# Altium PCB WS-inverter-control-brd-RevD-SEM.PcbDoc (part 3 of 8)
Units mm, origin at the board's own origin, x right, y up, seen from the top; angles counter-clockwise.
Board outline 270 x 105.92 mm, 6 copper layers (Top Layer, Int1 (Sign), Int2 (PWR), Int3 (GND), Int4 (Sign), Bottom Layer), stack 1.509 mm thick; 709 components, 375 nets, 2377 pads, 1332 vias.
Unrouted connection lines stored in the file: 55.
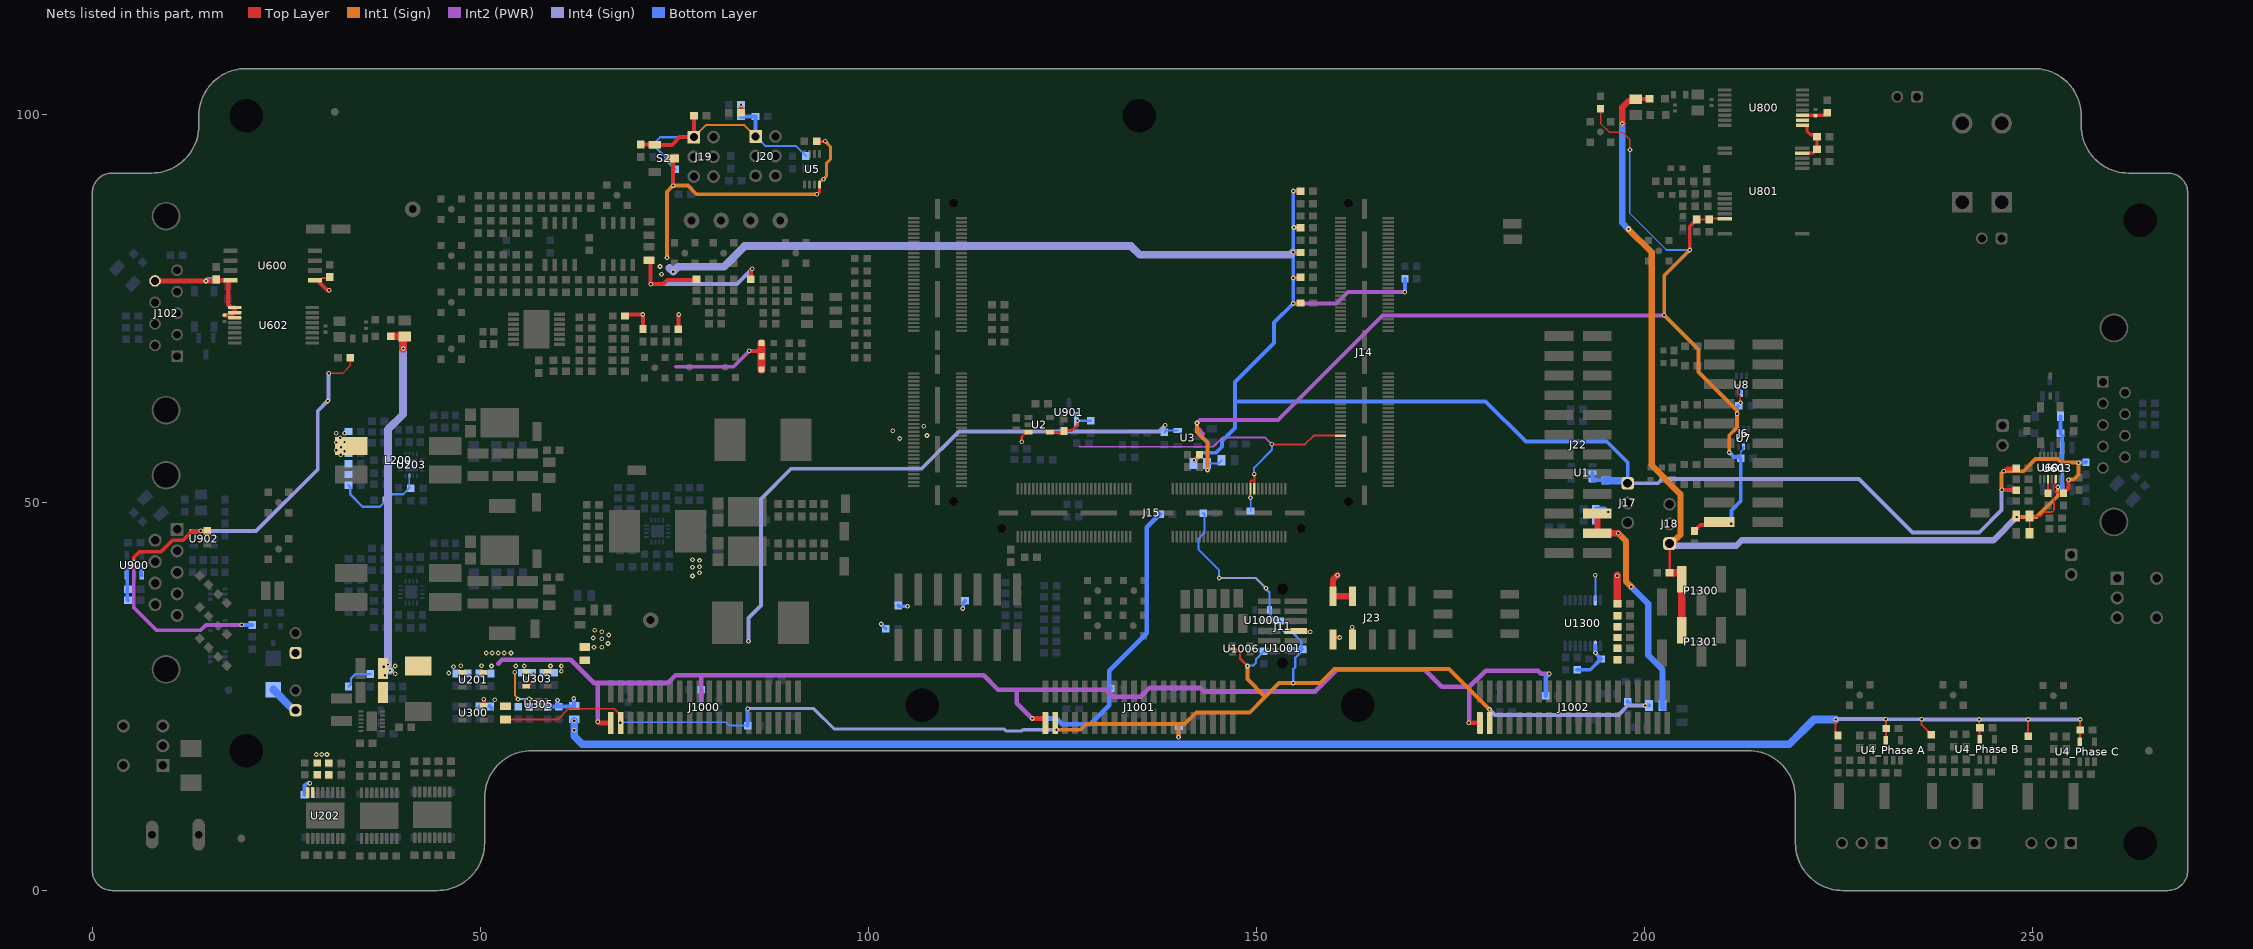
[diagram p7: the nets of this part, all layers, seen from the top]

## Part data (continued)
J107 J108: library part CMP-0093760-1, "Connector Header Through Hole 3 position 0.200\" (5.08mm)", Digikey Part Number=HPM-03-01-T-S-ND, Manufacturer=Samtec, Mouser Part Number=200-HPM0301TS, Operating Temperature Range="-55°C to +105°C"
J109 J110: library part CMP-0054970-1, "Header, 2.54mm, 2x1, Tin, TH", Color=Natural, Current_A=5A, Manufacturer="TE Connectivity", Supplier Part Number 1=A1921-ND, Voltage_V=250V
J600 J601: library part CMP-0075405-3, "Header, 100mil, 2x1, Gold, TH", Color=Black, Current_A=6.3A, Manufacturer=Samtec, Supplier Part Number 1=SAM1029-02-ND, Voltage_V=550V
J1000 J1001 J1002: library part CMP-0092627-1, "Connector Header Surface Mount 40 position 0.050\" (1.27mm)", Digikey Part Number=SAM11069-ND, Manufacturer=Samtec, Mouser Part Number=200-ESHF12001LDSM, Operating Temperature Range="-55°C to +125°C"
L200 L301: library part CMP-0080788-1, "Coupled inductor, 47 µH, 7.5 A, 0.065 ohm, SMD", Manufacturer=Coilcraft, ValueDisplayed=47µH
L300: library part CMP-0063383-1, "Inductor, Shielded, 2.2 uH, 8.1 A, 0.0183 ohm, AEC-Q200 Grade 1, SMD", Manufacturer=Vishay-Dale, Supplier Part Number 1=IHLP2525CZER2R2M5A-ND, Value1="0.0183 ohm", Value2=8.1A, ValueDisplayed=2.2uH
L400: library part CMP-0060638-1, "Inductor, Shielded Drum Core, Ferrite, 10 uH, 5.7 A, 0.02 ohm, SMD", Manufacturer=Coilcraft, Supplier Part Number 1=994-MSS1278T-103MLB, Value1="0.02 ohm", Value2=5.7A, ValueDisplayed=10uH
L401 L402: library part CMP-0061523-2, "Inductor, Shielded Drum Core, Ferrite, 22 uH, 4 A, 0.04 ohm, SMD", Manufacturer=Coilcraft, Supplier Part Number 1=994-MSS1278T-223MLB, Value1="0.04 ohm", Value2=4A, ValueDisplayed=22uH
L600 L601: library part CMP-0062430-2, "Inductor, Ferrite, 100 uH, 0.15 A, 2 ohm, SMD", Manufacturer=TDK, Supplier Part Number 1=445-3959-1-ND, Value1="2 ohm", Value2=0.15A, ValueDisplayed=100uH
L602 L800: library part CMP-1392-00025-2, Ambient Temperature Range High=85°C, Ambient Temperature Range Low=-40°C, Case/Package=SMD/SMT, Current Rating=550mA, DC Resistance (DCR)=300mΩ, Inductance=2.2µH, Manufacturer="Wurth Elektronik", Max Operating Temperature=125°C
LBL1200: library part CMP-0003625-1, "Thermal Transfer Printable Labels, 0.650\" W x 0.200\" H - 10,000 per roll", Manufacturer=Brady, Supplier Part Number 1=97C5133
LOGO1200: library part CMP-0074835-1, "IEC 61010-1 High Voltage Warning"
Logo1201: library part CMP-0074847-1, "FCC_disclaimer"
Logo1202: library part CMP-0074838-1, "Texas Instrument Corporate Signature"
Logo1203: library part CMP-0074769-1
NT200 NT300 NT400: library part CMP-0078142-6, "Single point connection between nets.", Manufacturer=N/A
P1300 P1301: library part CMP-1024-00239-1, "0.025\" SQ Post Header, Surface Mount, Vertical, -55 to 105 degC, 2.54 mm Pitch, 5-Pin, Male, RoHS", Manufacturer=Samtec, Temperature Range="-55 to 105 degC"
Q900: library part CMP-0077248-1, "MOSFET, N-CH, 20 V, 2.3 A, AEC-Q101, SOT-23", Alternate Manufacturer=None, Manufacturer="Infineon Technologies", Supplier Part Number 1=BSS806NEH6327XTSA1CT-ND, Value1="? ohm", Value2="1.7 nC"
"R1_Phase A" "R1_Phase B" "R1_Phase C" "R3_Phase A" "R3_Phase B" "R3_Phase C" R13 R25 R27 R28 R29 R30 R503 R504 R513 R521 R526 R527 R538 R545 R546 R550 R551 R562 R563 R564 R566 R568 R569 R600 R601 R608 R610 R804 R1000 R1001 R1002 R1003 R1004 R1005 R1006 R1007 R1008 R1009 R1010 R1011 R1012 R1013 R1014 R1015 R1016 R1017 R1018 R1034 R1036 R1040 R1042 R1304 Rjldc1 Rjldc2: library part CMP-0025697-4, "RES, 0, 5%, 0.1 W, AEC-Q200 Grade 0, 0603", Manufacturer=Vishay-Dale, Power_W=100mW, Supplier Part Number 1=541-0.0GCT-ND, TempCo="200 ppm/C", Tolerance_%=5%, Value2=0.1W, Value_Code=0000, ValueDisplayed=0
R2 R6: library part CMP-0022736-4, "RES, 100, 1%, 0.1 W, 0603", Manufacturer=Yageo, Power_W=100mW, Supplier Part Number 1=311-100HRCT-ND, TempCo="100 ppm/C", Tolerance_%=1%, Value2=0.1W, Value_Code=100R, ValueDisplayed=100
R4 R5 R31 R32 R33 R34 R35 R36 R37 R38 R39 R40 R41 R42 R43 R44 R45 R46 R47 R48 R49 R50 R51 R52 R53 R54 R55 R56 R57 R58 R308 R319 R320 R322 R505 R506 R507 R508 R509 R510 R516 R517 R529 R534 R548 R552 R553 R554 R555 R558 R559 R560 R561 R606 R613 R617 R618 R619 R905 R907 R1019 R1020 R1021 R1022 R1023 R1024 R1027 R1030: library part CMP-0021998-4, "RES, 10.0 k, 1%, 0.1 W, AEC-Q200 Grade 0, 0603", Manufacturer=Vishay-Dale, Power_W=100mW, Supplier Part Number 1=541-10.0KHCT-ND, TempCo="100 ppm/C", Tolerance_%=1%, Value2=0.1W, Value_Code=10k0, ValueDisplayed=10.0k
R7 R11 R12 R18 R514 R528 R547 R565 R570 R904: library part CMP-0081280-1, "RES, 47.0, 1%, 0.1 W, AEC-Q200 Grade 0, 0603", Manufacturer=Vishay-Dale, Power_W=100mW, Supplier Part Number 1=541-47.0HCT-ND, TempCo="100 ppm/C", Tolerance_%=1%, Value2=0.1W, Value_Code=47R0, ValueDisplayed=47.0
R8 R26: library part CMP-0022455-4, "RES, 4.64 k, 1%, 0.1 W, AEC-Q200 Grade 0, 0603", Manufacturer=Vishay-Dale, Power_W=100mW, Supplier Part Number 1=541-4.64KHCT-ND, TempCo="100 ppm/C", Tolerance_%=1%, Value2=0.1W, Value_Code=4k64, ValueDisplayed=4.64k
R9 R10 "R20_Phase A" "R20_Phase B" "R20_Phase C" R604 R609 R614 R615 R616: library part CMP-0022003-4, "RES, 10.0, 1%, 0.1 W, AEC-Q200 Grade 0, 0603", Manufacturer=Vishay-Dale, Power_W=100mW, Supplier Part Number 1=541-10.0HCT-ND, TempCo="100 ppm/C", Tolerance_%=1%, Value2=0.1W, Value_Code=10R0, ValueDisplayed=10.0
R10jump R103 R104 R105 R106 R113 R114 R115 R116 R324 R325 R539 R541 Rjump12v Rjumppre: library part CMP-0020833-2, "RES, 0, 1%, 0.5 W, 0805", Manufacturer=Keystone, Power_W=500mW, Supplier Part Number 1=36-5106CT-ND, TempCo=ppm/C, Tolerance_%=1%, Value2=0.5W, Value_Code=0
R14 R520 R525 R537 R544 R900 R906: library part CMP-0021991-4, "RES, 100, 1%, 0.1 W, AEC-Q200 Grade 0, 0603", Manufacturer=Vishay-Dale, Power_W=100mW, Supplier Part Number 1=541-100HCT-ND, TempCo="100 ppm/C", Tolerance_%=1%, Value2=0.1W, Value_Code=100R, ValueDisplayed=100
R15 R16 R59: library part CMP-0025817-4, "RES, 4.7 k, 5%, 0.1 W, AEC-Q200 Grade 0, 0603", Manufacturer=Vishay-Dale, Power_W=100mW, Supplier Part Number 1=541-4.7KGCT-ND, TempCo="200 ppm/C", Tolerance_%=5%, Value2=0.1W, Value_Code=4k70, ValueDisplayed=4.7k
R17: library part CMP-0022115-4, "RES, 1.15 k, 1%, 0.1 W, AEC-Q200 Grade 0, 0603", Manufacturer=Vishay-Dale, Power_W=100mW, Supplier Part Number 1=541-1.15KHCT-ND, TempCo="100 ppm/C", Tolerance_%=1%, Value2=0.1W, Value_Code=1k15, ValueDisplayed=1.15k
"R19_Phase A" "R19_Phase B" "R19_Phase C" "R21_Phase A" "R21_Phase B" "R21_Phase C": library part CMP-0078581-1, "RES, 1.00 k, 0.1%, 0.1 W, AEC-Q200 Grade 0, 0603", Manufacturer=Panasonic, Power_W=100mW, Supplier Part Number 1=P1.0KDBCT-ND, TempCo="25 ppm/C", Tolerance_%=0.1%, Value2=0.1W, Value_Code=1k00, ValueDisplayed=1.00k
"R22_Phase A" "R22_Phase B" "R22_Phase C" R321: library part CMP-0022599-4, "RES, 7.15 k, 1%, 0.1 W, AEC-Q200 Grade 0, 0603", Manufacturer=Vishay-Dale, Power_W=100mW, Supplier Part Number 1=541-7.15KHCT-ND, TempCo="100 ppm/C", Tolerance_%=1%, Value2=0.1W, Value_Code=7k15, ValueDisplayed=7.15k
"R23_Phase A" "R23_Phase B" "R23_Phase C": library part CMP-0015563-3, "RES, 27.0, 1%, 1 W, AEC-Q200 Grade 0, 2512", Manufacturer=Vishay-Dale, Power_W=1W, Supplier Part Number 1=541-27.0AFCT-ND, TempCo="100 ppm/C", Tolerance_%=1%, Value_Code=27R0, ValueDisplayed=27.0
"R24_Phase A" "R24_Phase B" "R24_Phase C": library part CMP-0860901-1, "RES, 24.9 k, 0.1%, 0.1 W, AEC-Q200 Grade 0, 0603", Manufacturer=Panasonic, Power_W=100mW, TempCo="25 ppm/C", Tolerance_%=0.1%, Value2=0.1W, Value_Code=24k9, ValueDisplayed=24.9k
R100 R101 R102: library part CMP-0022138-4, "RES, 1.00 M, 1%, 0.1 W, AEC-Q200 Grade 0, 0603", Manufacturer=Vishay-Dale, Power_W=100mW, Supplier Part Number 1=541-1.00MHCT-ND, TempCo="100 ppm/C", Tolerance_%=1%, Value2=0.1W, Value_Code=1M00, ValueDisplayed=1.00M
R235 R300 R400: library part CMP-0021990-4, "RES, 100 k, 1%, 0.1 W, AEC-Q200 Grade 0, 0603", Manufacturer=Vishay-Dale, Power_W=100mW, Supplier Part Number 1=541-100KHCT-ND, TempCo="100 ppm/C", Tolerance_%=1%, Value2=0.1W, Value_Code=100k
R236 R301 R402: library part CMP-0022597-4, "RES, 78.7 k, 1%, 0.1 W, AEC-Q200 Grade 0, 0603", Manufacturer=Vishay-Dale, Power_W=100mW, Supplier Part Number 1=541-78.7KHCT-ND, TempCo="100 ppm/C", Tolerance_%=1%, Value2=0.1W, Value_Code=78k7, ValueDisplayed=78.7k
R237 R302 R405: library part CMP-0022066-4, "RES, 15.0 k, 1%, 0.1 W, AEC-Q200 Grade 0, 0603", Manufacturer=Vishay-Dale, Power_W=100mW, Supplier Part Number 1=541-15.0KHCT-ND, TempCo="100 ppm/C", Tolerance_%=1%, Value2=0.1W, Value_Code=15k0, ValueDisplayed=15.0k
R238 R303 R306 R406 R417: library part CMP-0022509-4, "RES, 5.11 k, 1%, 0.1 W, AEC-Q200 Grade 0, 0603", Manufacturer=Vishay-Dale, Power_W=100mW, Supplier Part Number 1=541-5.11KHCT-ND, TempCo="100 ppm/C", Tolerance_%=1%, Value2=0.1W, Value_Code=5k11, ValueDisplayed=5.11k
R239 R304 R410 R426: library part CMP-0022511-4, "RES, 5.36 k, 1%, 0.1 W, AEC-Q200 Grade 0, 0603", Manufacturer=Vishay-Dale, Power_W=100mW, Supplier Part Number 1=541-5.36KHCT-ND, TempCo="100 ppm/C", Tolerance_%=1%, Value2=0.1W, Value_Code=5k36, ValueDisplayed=5.36k
R240 R305 R416 R515 R530 R533 R549: library part CMP-0022204-4, "RES, 20.0 k, 1%, 0.1 W, AEC-Q200 Grade 0, 0603", Manufacturer=Vishay-Dale, Power_W=100mW, Supplier Part Number 1=541-20.0KHCT-ND, TempCo="100 ppm/C", Tolerance_%=1%, Value2=0.1W, Value_Code=20k0, ValueDisplayed=20.0k
R241: library part CMP-0022371-4, "RES, 3.01 k, 1%, 0.1 W, AEC-Q200 Grade 0, 0603", Manufacturer=Vishay-Dale, Power_W=100mW, Supplier Part Number 1=541-3.01KHCT-ND, TempCo="100 ppm/C", Tolerance_%=1%, Value2=0.1W, Value_Code=3k01, ValueDisplayed=3.01k
R242 R309 R421 R427: library part CMP-0015019-3, "RES, 10.0, 1%, 0.75 W, AEC-Q200 Grade 0, 1210", Manufacturer=Vishay-Dale, Power_W=750mW, Supplier Part Number 1=541-10.0DCT-ND, TempCo="100 ppm/C", Tolerance_%=1%, Value2=0.75W, Value_Code=10R0, ValueDisplayed=10.0
R243 R310 R425 R518 R523 R535 R542: library part CMP-0022347-4, "RES, 34.8 k, 1%, 0.1 W, AEC-Q200 Grade 0, 0603", Manufacturer=Vishay-Dale, Power_W=100mW, Supplier Part Number 1=541-34.8KHCT-ND, TempCo="100 ppm/C", Tolerance_%=1%, Value2=0.1W, Value_Code=34k8, ValueDisplayed=34.8k
R244 R311: library part CMP-0022510-4, "RES, 5.23 k, 1%, 0.1 W, AEC-Q200 Grade 0, 0603", Manufacturer=Vishay-Dale, Power_W=100mW, Supplier Part Number 1=541-5.23KHCT-ND, TempCo="100 ppm/C", Tolerance_%=1%, Value2=0.1W, Value_Code=5k23, ValueDisplayed=5.23k
R245 R312 R429: library part CMP-0022237-4, "RES, 24.9 k, 1%, 0.1 W, AEC-Q200 Grade 0, 0603", Manufacturer=Vishay-Dale, Power_W=100mW, Supplier Part Number 1=541-24.9KHCT-ND, TempCo="100 ppm/C", Tolerance_%=1%, Value2=0.1W, Value_Code=24k9, ValueDisplayed=24.9k
R246 R313: library part CMP-0022024-4, "RES, 121 k, 1%, 0.1 W, AEC-Q200 Grade 0, 0603", Manufacturer=Vishay-Dale, Power_W=100mW, Supplier Part Number 1=541-121KHCT-ND, TempCo="100 ppm/C", Tolerance_%=1%, Value2=0.1W, Value_Code=121k
R247 R314 R428: library part CMP-0022221-4, "RES, 22.6 k, 1%, 0.1 W, AEC-Q200 Grade 0, 0603", Manufacturer=Vishay-Dale, Power_W=100mW, Supplier Part Number 1=541-22.6KHCT-ND, TempCo="100 ppm/C", Tolerance_%=1%, Value2=0.1W, Value_Code=22k6, ValueDisplayed=22.6k
R248 R315 R431: library part CMP-0022512-4, "RES, 5.49 k, 1%, 0.1 W, AEC-Q200 Grade 0, 0603", Manufacturer=Vishay-Dale, Power_W=100mW, Supplier Part Number 1=541-5.49KHCT-ND, TempCo="100 ppm/C", Tolerance_%=1%, Value2=0.1W, Value_Code=5k49, ValueDisplayed=5.49k
R249 R316 R432: library part CMP-0022447-4, "RES, 49.9 k, 1%, 0.1 W, AEC-Q200 Grade 0, 0603", Manufacturer=Vishay-Dale, Power_W=100mW, Supplier Part Number 1=541-49.9KHCT-ND, TempCo="100 ppm/C", Tolerance_%=1%, Value2=0.1W, Value_Code=49k9, ValueDisplayed=49.9k
R250 R317 R433: library part CMP-0022536-4, "RES, 61.9 k, 1%, 0.1 W, AEC-Q200 Grade 0, 0603", Manufacturer=Vishay-Dale, Power_W=100mW, Supplier Part Number 1=541-61.9KHCT-ND, TempCo="100 ppm/C", Tolerance_%=1%, Value2=0.1W, Value_Code=61k9, ValueDisplayed=61.9k
R251 R318 R434 R501 R502: library part CMP-0022268-4, "RES, 2.00 k, 1%, 0.1 W, AEC-Q200 Grade 0, 0603", Manufacturer=Vishay-Dale, Power_W=100mW, Supplier Part Number 1=541-2.00KHCT-ND, TempCo="100 ppm/C", Tolerance_%=1%, Value2=0.1W, Value_Code=2k00, ValueDisplayed=2.00k
R307 R522 R540: library part CMP-0022410-4, "RES, 40.2 k, 1%, 0.1 W, AEC-Q200 Grade 0, 0603", Manufacturer=Vishay-Dale, Power_W=100mW, Supplier Part Number 1=541-40.2KHCT-ND, TempCo="100 ppm/C", Tolerance_%=1%, Value2=0.1W, Value_Code=40k2, ValueDisplayed=40.2k
R430: library part CMP-0022581-4, "RES, 71.5 k, 1%, 0.1 W, AEC-Q200 Grade 0, 0603", Manufacturer=Vishay-Dale, Power_W=100mW, Supplier Part Number 1=541-71.5KHCT-ND, TempCo="100 ppm/C", Tolerance_%=1%, Value2=0.1W, Value_Code=71k5, ValueDisplayed=71.5k
R500 R556 R557: library part CMP-0022558-4, "RES, 6.04 k, 1%, 0.1 W, AEC-Q200 Grade 0, 0603", Manufacturer=Vishay-Dale, Power_W=100mW, Supplier Part Number 1=541-6.04KHCT-ND, TempCo="100 ppm/C", Tolerance_%=1%, Value2=0.1W, Value_Code=6k04, ValueDisplayed=6.04k
R511 R512: library part CMP-0022552-4, "RES, 68.1 k, 1%, 0.1 W, AEC-Q200 Grade 0, 0603", Manufacturer=Vishay-Dale, Power_W=100mW, Supplier Part Number 1=541-68.1KHCT-ND, TempCo="100 ppm/C", Tolerance_%=1%, Value2=0.1W, Value_Code=68k1, ValueDisplayed=68.1k
R519 R524 R536 R543 R612 R1300 R1301 R1302 R1303 R1305 R1306 R1307: library part CMP-0022109-5, "RES, 1.00 k, 1%, 0.1 W, AEC-Q200 Grade 0, 0603", Manufacturer=Vishay-Dale, Power_W=100mW, Supplier Part Number 1=541-1.00KHCT-ND, TempCo="100 ppm/C", Tolerance_%=1%, Value2=0.1W, Value_Code=1k00, ValueDisplayed=1.00k
R602 R603 R605 R607: library part CMP-0022533-4, "RES, 60.4, 1%, 0.1 W, AEC-Q200 Grade 0, 0603", Manufacturer=Vishay-Dale, Power_W=100mW, Supplier Part Number 1=541-60.4HCT-ND, TempCo="100 ppm/C", Tolerance_%=1%, Value2=0.1W, Value_Code=60R4, ValueDisplayed=60.4
R620 R800: library part CMP-0022852-5, "RES, 18.0 k, 1%, 0.1 W, 0603", Manufacturer=Yageo, Power_W=100mW, Supplier Part Number 1=311-18.0KHRCT-ND, TempCo="100 ppm/C", Tolerance_%=1%, Value2=0.1W, Value_Code=18k0, ValueDisplayed=18.0k
R901: library part CMP-0022090-4, "RES, 17.8 k, 1%, 0.1 W, AEC-Q200 Grade 0, 0603", Manufacturer=Vishay-Dale, Power_W=100mW, Supplier Part Number 1=541-17.8KHCT-ND, TempCo="100 ppm/C", Tolerance_%=1%, Value2=0.1W, Value_Code=17k8, ValueDisplayed=17.8k
R902: library part CMP-0022324-4, "RES, 30.1 k, 1%, 0.1 W, AEC-Q200 Grade 0, 0603", Manufacturer=Vishay-Dale, Power_W=100mW, Supplier Part Number 1=541-30.1KHCT-ND, TempCo="100 ppm/C", Tolerance_%=1%, Value2=0.1W, Value_Code=30k1, ValueDisplayed=30.1k
R903: library part CMP-0021042-3, "RES, 20.0 k, 1%, 0.125 W, AEC-Q200 Grade 0, 0805", Manufacturer=Vishay-Dale, Power_W=125mW, Supplier Part Number 1=541-20.0KCCT-ND, TempCo="100 ppm/C", Tolerance_%=1%, Value2=0.125W, Value_Code=20k0, ValueDisplayed=20.0k
S1: library part CMP-0002123-2, "SLIDE SWITCH DPDT  .1A, SMT", CurrentRating_mA=100A, Manufacturer="Copal Electronics", Supplier Part Number 1=CAS220JCT-ND
S2: library part CMP-0002139-2, "Switch, Slide, SPDT  100mA, SMT", CurrentRating_mA=100A, Manufacturer="Copal Electronics", Supplier Part Number 1=CAS120JCT-ND
S100 S101: library part CMP-0097544-1, "Switch Toggle SPDT 3A 120V", Coil Resistance_ohm=20mΩ, Contact Current Rating=3A, Digikey Part Number=EG5778-ND, Manufacturer=E-Switch, Mouser Part Number=612-200MSP1T1B2M6QE, Operating Temperature Range="-30°C to +85°C"
S1300: library part CMP-0002269-1, "Switch, SPST, Slide, Off-On, 3 Pos, 0.1A, 20V, SMD", CurrentRating_mA=100A, Manufacturer="CTS Electrocomponents", Supplier Part Number 1=CT2193MST-ND
TP1 TP2 TP3 TP4 TP5 TP6 TP7 TP8 TP9 TP10 TP201 TP202 TP301 TP302 TP400 TP401 TP402 TP403 TP404 TP600 TP601 TP602 TP603 TP604 TP900 TP_alert TP_voc: library part CMP-0067620-1, "PC Test Point, SMT", Manufacturer="TE Connectivity", Supplier Part Number 1=A106145CT-ND
TP100 TP101 TP500 TP501 TP502 TP503: library part CMP-0055137-2, "Test Point, Miniature, Red, TH", Color=Red, Manufacturer="Keystone Electronics", Supplier Part Number 1=36-5000-ND
TP200 TP300: library part CMP-0055152-2, "Test Point, Miniature, SMT", Manufacturer="Keystone Electronics", Supplier Part Number 1=36-5015TR-ND
U1: library part CMP-0051001-1, "Single 3-Input Positive OR-AND Gate, DBV0006A, LARGE T&R", F @ Nom Voltage(Max)(Mhz)=150, Generic Part Number=SN74LVC1G3208, ICC @ Nom Voltage(Max)(mA)=0.01, Manufacturer="Texas Instruments", Operating Temperature Range(C)="-40 to 125,-40 to 85", Rating=Catalog, tpd @ Nom Voltage(Max)(ns)=17.5,7.5,5.9,4.5, Voltage(Nom)(V)=1.8,2.5,3.3,5
U2: library part CMP-0066190-1, "Low-Drift, Low-Power, Dual-Output VREF and VREF/2 Voltage Reference, DDC0005A (SOT-23-T-5)", Alternate Manufacturer="Texas Instruments", Alternate PartNumber=REF2033AIDDCT
U3 "U4_Phase A" "U4_Phase B" "U4_Phase C" U902: library part CMP-0120546-1, "Automotive, single-channel, 5.5-V 1-MHz rail-to-rail input and output operational amplifier 5-SOT-23 -40 to 125", Digikey Part Number=296-TLV9001QDBVRQ1CT-ND, Input Bias Current=0.000005uA, Input Offset Voltage=0.4mV, Manufacturer="Texas Instruments", Max Dual Supply Voltage=2.75V, Max Supply Voltage=5.5V, Min Dual Supply Voltage=900mV, Min Supply Voltage=1.8V, Mouser Part Number=595-TLV9001QDBVRQ1, Nominal Supply Current=60uA, Operating Temperature Range="-40°C to +125°C", Output Current Per Channel=40mA, Voltage Gain=130dB
U5: library part CMP-0051817-1, "Automotive Catalog Dual Bus Buffer Gate with 3-State Outputs, DCT0008A, LARGE T&R", F @ Nom Voltage(Max)(Mhz)=150, Generic Part Number=SN74LVC2G125-Q1, ICC @ Nom Voltage(Max)(mA)=0.01, Manufacturer="Texas Instruments", Operating Temperature Range(C)="-40 to 85", Rating=Automotive, tpd @ Nom Voltage(Max)(ns)=9.1,4.8,4.3,3.7, Voltage(Nom)(V)=1.8,2.5,3.3,5
U7 U8: library part CMP-0051218-3, "Automotive Catalog Single 3-Input Positive-AND Gate, DCK0006A (SOT-SC70-6)", F @ Nom Voltage(Max)(Mhz)=150, Generic Part Number=SN74LVC1G11-Q1, ICC @ Nom Voltage(Max)(mA)=0.01, Manufacturer="Texas Instruments", Operating Temperature Range="-40 to 85 C", Rating=Automotive, tpd @ Nom Voltage(Max)(ns)=17.2,6.9,4.9,3.5, Voltage(Nom)(V)=1.8,2.5,3.3,5
U201 U300: library part CMP-0079175-1, "Automotive High-Voltage Ultralow-IQ Low-Dropout Regulator, DBV0005A (SOT-23-5)", Alternate Manufacturer="Texas Instruments"
U202 U301 U401: library part CMP-0086311-1, "40V, 2A Integrated Ideal Diode with Over-Voltage & Over-Current protection, PWP0016J (HTSSOP-16)", Alternate Manufacturer="Texas Instruments"
U203 U304: library part CMP-0091836-5, "2.2-MHz Wide VIN 85-V Boost/Sepic/Flyback Converter with Dual Random Spread Spectrum", Manufacturer="Texas Instruments", Max Supply Voltage=60V, Min Supply Voltage=1.5V, Nominal Supply Current=670uA, Operating Temperature Range="-40°C to +150°C", Output Voltage=83V, Switching Frequency=100-2200kHz
U302: library part CMP-0097736-1, "Buck Switching Regulator IC Positive Adjustable 1V 1 Output 3.25A 12-WFDFN Exposed Pad", Digikey Part Number=296-LM63635DQDRRRQ1CT-ND, Manufacturer="Texas Instruments", Max Supply Voltage=36V, Min Supply Voltage=3.5V, Mouser Part Number=595-LM63635DQDRRRQ1, Nominal Supply Current=23uA, Operating Temperature Range="-40°C to +150°C", Output Voltage=3.3/5/1-20V, Switching Frequency=400/2100/250-2200kHz
U303: library part CMP-0860155-1, "Automotive capacitor-free 300-mA LDO regulator with foldback current limit for portable devices, DBV0005A (SOT-23-5)", Alternate Manufacturer="Texas Instruments", Operating Temperature Range="-40 to 125,-40 to 150 C", Rating=Automotive
U305: library part CMP-0078865-1, "Capacitor-Free, 300-mA, Low-Dropout Regulator for Automotive, DRV0006A (WSON-6)", Alternate Manufacturer="Texas Instruments"
U402: library part CMP-0861102-1, "2.2MHz Wide VIN Boost/Sepic/Flyback Converter with Dual Random Spread Spectrum, RTE0016K (WQFN-16)", Alternate Manufacturer="Texas Instruments"
U500: library part CMP-0861002-1, "24-V, High-Current, Wide-Bandwidth, Dual Operational Amplifier, PWP0014H (HTSSOP-14)", Alternate Manufacturer="Texas Instruments"
U501 U502: library part CMP-0094081-1, "40-V, dual 4.5MHz, rail-to-rail input/output, low-offset-voltage, low-noise op amp 8-SOIC -40 to 125", Digikey Part Number=296-OPA2991IDRCT-ND, Input Bias Current=0.00001uA, Input Offset Voltage=0.125mV, Manufacturer="Texas Instruments", Max Dual Supply Voltage=20V, Max Supply Voltage=40V, Min Dual Supply Voltage=1.35V, Min Supply Voltage=2.7V, Mouser Part Number=595-OPA2991IDR, Nominal Supply Current=560uA, Operating Temperature Range="-40°C to +125°C", Output Current Per Channel=75mA, Voltage Gain=120dB
U600: library part CMP-0096963-1, "Automotive Isolated CAN Transceiver With 70-V Bus Fault Protection and Flexible Data Rate", Digikey Part Number=296-ISO1042QDWVRQ1CT-ND, Manufacturer="Texas Instruments", Max Supply Voltage=5.5V, Min Supply Voltage=1.71V, Mouser Part Number=595-ISO1042QDWVRQ1, Operating Temperature Range="-40°C to +125°C"
U601: library part CMP-0089855-1, "Low-Power Fault Protected CAN FD Transceiver with INH and WAKE", Manufacturer="Texas Instruments", Max Supply Voltage=28V, Min Supply Voltage=1.7V, Operating Temperature Range="-40°C to +125°C"
U602 U800: library part CMP-0120108-2, "1.5W, High-Density, >5 kVRMS Isolated DC-DC Converter", Manufacturer="Texas Instruments", Max Supply Voltage=5.5V, Min Supply Voltage=4.5V, Operating Temperature Range="-40°C to +125°C", Output Voltage=5/5.5V
U603: library part CMP-0091357-1, "Fault-Protected LIN Transceiver with Inhibit and Wake", Manufacturer="Texas Instruments", Max Supply Voltage=36V, Min Supply Voltage=4.5V, Nominal Supply Current=300-1200uA, Operating Temperature Range="-40°C to +125°C"
U604 U605: library part CMP-0093261-1, "24-V, 2-Channel ESD Protection Diode for In-Vehicle Networks", Breakdown Voltage=25.5V, Clamping Voltage=32V, Manufacturer="Texas Instruments", Operating Temperature Range="-55°C to +150°C", ValueDisplayed=3pF
U801: library part CMP-0034316-3, "Isolated Amplifiers for direct HV Sensing", Manufacturer="Texas Instruments", Operating Temperature Range=to
U900: library part CMP-0096536-1, "Automotive, 70-mA, 40-V, Voltage-Tracking LDO With 5-mV Tracking Tolerance, SOT23-5", Dropout Voltage=500mV, Manufacturer="Texas Instruments", Max Supply Voltage=40V, Min Supply Voltage=3V, Nominal Supply Current=600-800uA, Operating Temperature Range="-40°C to +125°C", Output Voltage=2-40V
U901: library part CMP-04948-000108-1, "IC TEMP SENSOR", Manufacturer="Texas Instruments"
U1000: library part CMP-0051613-2, "Single 2-Input Positive-OR Gate, DBV0005A (SOT-23-5)", F @ Nom Voltage(Max)(Mhz)=75, Generic Part Number=SN74AHC1G32, ICC @ Nom Voltage(Max)(mA)=0.01, Manufacturer="Texas Instruments", Operating Temperature Range="-40 to 125 C", Rating=Catalog, tpd @ Nom Voltage(Max)(ns)=13,8.5, Voltage(Nom)(V)=3.3,5
U1001 U1006: library part CMP-0051255-3, "Single 3-Input Positive-OR Gate, DCK0006A (SOT-SC70-6)", F @ Nom Voltage(Max)(Mhz)=150, Generic Part Number=SN74LVC1G332, ICC @ Nom Voltage(Max)(mA)=0.01, Manufacturer="Texas Instruments", Operating Temperature Range="-40 to 125,-40 to 85 C", Rating=Catalog, tpd @ Nom Voltage(Max)(ns)=17.2,6.2,4.8,3.5, Voltage(Nom)(V)=1.8,2.5,3.3,5
U1300: library part CMP-0067443-1, "6-Bit Bidirectional Voltage-Level Translator with Auto Direction Sensing and +/-15-kV ESD Protect, PW0016A (TSSOP-16)", Alternate Manufacturer="Texas Instruments"

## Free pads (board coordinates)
  round 0 hole 4.318 unplated mask+4: 1(19.812,18.034) 1(19.812,99.822) 1(106.934,23.876) 1(134.874,99.822) 1(163.068,23.876) 1(263.906,6.096) 1(263.906,86.36)

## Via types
v1: diameter 0.6, hole 0.3, Top Layer to Bottom Layer, tented both sides, 1302 vias
v2: diameter 0.5, hole 0.2, Top Layer to Bottom Layer, 17 vias
v3: diameter 0.6, hole 0.3, Top Layer to Bottom Layer, 12 vias
v4: diameter 0.8, hole 0.5, Top Layer to Bottom Layer, tented both sides, 1 vias

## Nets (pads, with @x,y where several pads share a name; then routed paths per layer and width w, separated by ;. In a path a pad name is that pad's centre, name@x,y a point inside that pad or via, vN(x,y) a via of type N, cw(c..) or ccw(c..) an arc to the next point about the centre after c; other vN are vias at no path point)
3V3_L_SMCU_IN_1: C19.1 C20.1 J22.20 J22.22 R115.2 | length 33.6
  Top Layer w0.8: J22.20@193.943,48.576 J22.22@193.943,46.036 196.608,46.036 v1(196.621,46.05)
  Int1 (Sign) w0.8: v1(196.621,46.05) 197.637,45.034 197.637,39.802 v1(198.295,39.144)
  Bottom Layer w0.5: C20.1@193.737,47.614 C19.1@193.737,49.214 194.884,49.214 v1(195.316,48.782)
  Bottom Layer w0.8: v1@198.212,39.227 v1(198.295,39.144) 200.482,36.957 200.482,30.328 202.323,28.487 R115.2@202.323,23.836 202.323,23.631 R115.2@202.418,23.536
3V3_LDC_19: C3v3ldc2.1 C3v3ldc.1 C22.1 J19.1 J20.1 R31.2 R32.2 R35.2 R36.2 R55.2 R58.2 S2.1 | length 43.8
  Top Layer w0.5: R58.2@70.643,96.136 70.668,96.111 72.468,96.111 S2.1@72.493,96.086 74.693,96.086 75.683,97.076 J19.1@77.503,97.076 77.543,97.116 R31.2@77.543,99.836 ; C3v3ldc.1@83.593,100.211 v1(83.593,101.236)
  Int1 (Sign) w0.25: J19.1@77.503,97.076 79.063,98.636 84.013,98.636 J20.1@85.473,97.176
  Bottom Layer w0.25: J20.1@85.473,97.176 86.688,95.961 90.643,95.961 R55.2@91.943,94.661
  Bottom Layer w0.3: R36.2@75.099,92.936 75.099,92.961 74.774,93.286 74.749,93.286 73.843,94.192 73.843,94.511 72.593,95.761 72.568,95.761 72.243,96.086 72.243,96.136 73.183,97.076 J19.1@77.503,97.076
  Bottom Layer w0.5: v1(83.593,101.236) C3v3ldc2.1@83.593,99.736 R35.2@85.443,99.736 85.443,97.206 J20.1@85.473,97.176
5V_iso_AMC_9: C803.1 C808.2 C809.2 C811.2 U800.9 U800.10 U800.11 U801.5 | length 10.1
  Top Layer w0.4: U801.5@220.318,95.011 221.728,95.011 222.228,95.511 C808.2@222.253,95.511 C809.2@222.253,97.111 221.978,97.386 221.393,97.386 220.951,97.829 220.951,98.598 220.946,98.603 U800.9@220.35,98.603 ; U800.11@220.35,99.903 223.235,99.903 223.543,100.211 C811.2@223.543,100.236
+3.3V: C21.1 C600.1 C612.2 C900.1 C901.2 C905.2 C1300.1 Cu5c.1 D1.2 D2.2 D3.2 J11.8 J17.1 J23.8 J23.10 R4.2 R14.1 R15.1 R16.2 R37.2 R38.2 R39.2 R40.2 R41.2 R42.2 R104.1 R324.1 R507.2 R539.1 R552.1 R553.1 R562.2 R566.2 R606.1 R613.2 R617.1 R620.2 R905.2 R1303.1 S2.2 U1.5 U1.6 U5.8 U600.1 U601.5 U900.1 U900.3 U902.5 U1300.2 | length 471.8
  Top Layer w0.18: C905.2@14.806,46.315 C905.2@14.808,46.317 ; U5.8@93.718,90.961 U5.8@93.718,91.286 ; v1@94.428,96.536 v1@94.437,96.545
  Top Layer w0.2: v1(30.443,66.636) 32.243,66.636 33.243,67.636 R620.2@33.243,68.636 ; U601.5@253,53 252.95,52.95 252.95,52.396 252.765,52.211 252.765,51.575 253.071,51.269 253.931,51.269 C612.2@254,51.2
  Top Layer w0.25: U600.1@29.293,78.631 29.598,78.936 30.489,78.936 C600.1@30.601,79.049
  Top Layer w0.4: v1(13.985,46.34) 13.996,46.329 14.793,46.329 C905.2@14.806,46.315 ; Cu5c.1@93.343,96.536 v1@94.428,96.536 ; v1(93.345,89.713) 93.391,89.713 93.718,90.04 U5.8@93.718,90.961 ; U5.8@93.718,91.286 94.062,91.63 94.17,91.63 v1(94.209,91.669)
  Top Layer w0.5: v1(5.33,42.334) 5.33,42.923 6.055,43.648 8.864,43.648 10.352,45.136 11.684,45.136 12.888,46.34 v1(13.985,46.34) ; U600.1@28.693,78.631 28.743,78.631 28.793,78.581 29.343,78.581 29.343,78.275 30.281,77.336 v1(30.543,77.336) ; R507.2@68.643,74.036 68.823,74.216 v1@70.916,74.216 ; v1(70.943,74.216) 70.957,74.203 R566.2@70.957,72.357 ; R539.1@71.738,81.211 71.924,81.026 71.924,78.156 v1(71.943,78.136) 73.556,78.136 74.106,78.686 77.784,78.686 R553.1@77.85,78.753 ; v1@74.826,90.853 S2.2@74.826,94.303 ; R562.2@75.521,72.336 75.54,72.356 75.54,74.197 v1(75.56,74.216) ; v1(84.643,69.536) 86.214,69.536 ; R552.1@84.85,78.753 84.85,79.943 v1(85.017,80.11) ; v1(141.947,55.436) 141.972,55.436 142.672,56.136 R4.2@142.672,56.161 ; v1(154.743,75.636) 154.762,75.656 155.639,75.656 R39.2@155.695,75.711 ; v1(154.743,78.936) 154.762,78.956 155.639,78.956 R41.2@155.695,79.011 ; v1(154.743,82.236) 154.756,82.224 155.683,82.224 R38.2@155.695,82.211 ; v1(154.743,90.136) 154.756,90.124 155.683,90.124 R37.2@155.695,90.111 ; v1(154.843,85.436) 154.856,85.424 155.683,85.424 R40.2@155.695,85.411 ; J11.8@155.08,33.448 155.192,33.336 v1(156.943,33.336) ; J23.10@159.863,32.342 159.863,32.389 160.07,32.596 v1(160.725,32.596) ; v1(162.343,33.936) 162.343,32.402 J23.8@162.403,32.342 ; v1(246.03,51.623) 247.877,51.623 R617.1@247.9,51.6 ; v1(246.282,54.025) 246.309,54.025 246.685,54.4 R606.1@247.9,54.4 ; C612.2@254,51.2 254,51.225 254.644,51.869 254.644,52.924 v1(254.649,52.929)
  Top Layer w1: D1.2@86.214,67.136 D2.2@86.214,68.836 86.214,69.536 D3.2@86.214,70.536
  Int2 (PWR) w0.5: v1(5.33,42.334) 5.33,36.452 8.245,33.536 13.943,33.536 14.643,34.236 v1(19.243,34.236) ; 75.198,67.491 82.598,67.491 v1(84.643,69.536) ; v1(154.743,75.636) 160.314,75.636 161.782,77.104 v1(169.102,77.104)
  Int1 (Sign) w0.4: v1(94.209,91.669) 94.59,92.05 94.59,93.686 95.123,94.219 95.123,95.842 v1(94.433,96.532)
  Int1 (Sign) w0.5: v1(74.043,81.536) 74.043,90.036 v1(74.843,90.836) 76.752,90.836 77.876,89.713 v1(93.345,89.713) ; v1(246.03,51.623) 246.03,53.746 246.282,53.997 v1(246.282,54.025) 248.831,54.025 250.41,55.603 253.276,55.603 253.743,55.136 v1(255.943,55.136) 255.943,53.568 255.323,52.948 254.668,52.948 v1(254.649,52.929)
  Int4 (Sign) w0.5: v1(13.985,46.34) 15.254,46.34 15.285,46.309 21.083,46.309 29.043,54.269 29.043,61.793 v1(30.321,63.071) 30.321,63.098 30.443,63.22 v1(30.443,66.636) ; v1@71.962,78.156 83.062,78.156 v1(85.017,80.11) ; J17.1@197.843,52.476 201.727,52.476 202.297,53.047 227.633,53.047 234.543,46.136 243.143,46.136 246.03,49.023 v1(246.03,51.623)
  Int4 (Sign) w1: 74.359,80.221 v1(74.843,79.736) 75.496,80.389 81.396,80.389 84.043,83.036 133.843,83.036 134.961,81.918 154.398,81.918 154.716,82.236 v1(154.743,82.236)
  Bottom Layer w0.18: U902.5@13.043,46.303 U902.5@13.058,46.319
  Bottom Layer w0.4: U902.5@13.058,46.319 13.073,46.304 13.09,46.322 13.966,46.322 v1(13.985,46.34)
  Bottom Layer w0.5: C901.2@4.6,37.4 4.5,37.5 4.5,40.55 U900.3@4.45,40.6 4.5,40.65 4.5,41.3 4.8,41.6 5.367,41.6 ; v1(5.33,42.334) 5.367,42.297 5.367,41.6 ; U900.1@6.35,40.6 6.3,40.65 6.3,41.357 6.057,41.6 5.367,41.6 ; v1(19.243,34.236) 19.28,34.2 R905.2@20.6,34.2 ; v1(101.643,34.336) R16.2@102.243,33.736 ; R15.1@103.843,36.736 103.943,36.636 v1(105.043,36.636) ; v1(112.143,36.349) 112.143,36.376 112.224,36.457 112.224,37.108 R14.1@112.443,37.326 ; R104.1@141.947,55.361 v1(141.947,55.436) ; R104.1@142.018,55.366 143.067,56.415 144.782,56.415 145.55,57.183 145.55,57.918 147.223,59.591 147.223,63.036 ; v1(154.743,90.136) v1(154.743,82.236) v1(154.743,78.936) v1(154.743,75.636) 152.284,73.177 152.284,70.577 147.223,65.516 147.223,63.036 ; v1(169.102,77.104) 169.102,77.132 169.143,77.172 169.143,78.835 R42.2@169.145,78.836 ; R1303.1@191.326,28.442 193.024,28.442 194.418,29.836 193.675,30.58 U1300.2@193.675,31.5 ; U1.5@193.318,53.836 U1.6@193.318,52.886 193.343,52.861 194.918,52.861 C21.1@194.943,52.836 ; J17.1@197.843,52.476 197.843,55.136 195.137,57.843 184.737,57.843 179.543,63.036 147.223,63.036 ; v1(255.943,55.136) 256.836,55.136 R613.2@256.9,55.2
  Bottom Layer w1: C21.1@194.943,52.836 195.483,52.836 195.518,52.801 197.518,52.801 J17.1@197.843,52.476
  other v1: 193.697,30.624 64.643,31.336 65.643,31.336 66.45,31.834 65.643,32.436 64.543,32.536 66.55,32.934 65.643,33.336 64.743,33.536 73.345,79.41 73.145,80.41
+3.3V_C-V: "C10_Phase A.1" "C10_Phase B.1" "C10_Phase C.1" "R19_Phase A.2" "R19_Phase B.2" "R19_Phase C.2" "U4_Phase A.5" "U4_Phase B.5" "U4_Phase C.5" C9.1 C15.1 C23.1 C24.1 C804.1 C805.1 J6.11 R103.1 R104.2 R325.1 R800.2 U3.5 U7.5 U8.5 U801.14 | length 454.1
  Top Layer w0.2: R800.2@194.343,100.736 194.343,98.851 195.457,97.736 197.143,97.736 198.136,96.744 v1(198.136,95.436) ; v1(212.043,64.936) 212.043,64.015 212.373,63.685 v1(212.373,62.871)
  Top Layer w0.25: C804.1@206.75,86.478 C805.1@208.35,86.478 208.475,86.603 U801.14@210.375,86.603 ; v1(224.643,22.036) 224.643,20.285 224.95,19.978 ; 231.1,19.378 v1(231.1,22.079) ; v1(235.722,22.058) 235.722,21.331 236.95,20.103 236.95,20.078 ; v1(243.143,22.036) 243.143,21.085 243.25,20.978 243.2,20.928 243.2,19.478 ; v1(249.443,22.036) 249.443,19.885 249.45,19.878 ; 256.1,19.178 256.1,20.628 256.15,20.678 256.143,20.685 v1(256.143,22.036)
  Top Layer w0.5: v1(205.843,82.536) 205.843,85.546 206.75,86.453 C804.1@206.75,86.478 ; C15.1@206.443,46.336 206.443,46.361 206.668,46.586 206.693,46.586 207.198,47.091 209.258,47.091 J6.11@209.643,47.476
  Int2 (PWR) w0.5: 143.135,58.845 142.334,59.646 v1(142.334,60.249) 142.334,60.255 142.715,60.636 152.775,60.636 166.256,74.118 v1@202.529,74.118
  Int1 (Sign) w0.5: v1(142.334,60.249) 142.334,59.076 143.691,57.719 v1(143.691,54.176) ; v1(202.556,74.118) 202.556,79.249 v1(205.843,82.536) ; v1@202.575,74.099 206.943,69.731 206.943,66.836 211.943,61.836 v1(211.943,61.436) 211.943,59.677 210.93,58.664 210.93,56.449 v1(210.943,56.436)
  Int4 (Sign) w0.5: v1(84.543,32.136) 84.543,35.136 86.143,36.736 86.143,50.436 90.048,54.341 106.848,54.341 111.664,59.157 137.458,59.157 v1(138.243,59.942) ; v1(224.643,22.036) 224.662,22.056 224.733,22.056 224.757,22.079 v1(231.1,22.079) 231.111,22.069 235.711,22.069 v1(235.722,22.058) 235.732,22.047 243.132,22.047 v1(243.143,22.036) v1(249.443,22.036) v1(256.143,22.036)
  Bottom Layer w0.2: C9.1@138.243,59.136 v1(138.243,59.942) ; R104.2@143.623,55.036 143.691,54.968 v1(143.691,54.176) ; v1(198.136,95.436) 198.136,87.244 202.843,82.536 v1(205.843,82.536) ; v1(212.043,64.936) 212.043,64.847 212.423,64.467 212.423,64.149 U8.5@212.523,64.049 ; C23.1@212.152,62.477 212.152,62.65 v1(212.373,62.871)
  Bottom Layer w0.25: C9.1@138.143,59.036 138.243,59.136 138.393,59.286 U3.5@139.843,59.286 ; R104.2@143.623,55.036 145.123,55.036 145.493,55.406 R103.1@145.493,55.436 ; C24.1@212.414,55.692 212.414,56.542 212.698,56.825 212.698,57.099 U7.5@212.773,57.174
  Bottom Layer w0.5: v1@210.962,56.417 211.533,55.847 212.26,55.847 C24.1@212.414,55.692 212.414,50.207 211.199,48.992 v1(211.199,47.261) ; v1(211.943,61.436) 211.943,62.268 C23.1@212.152,62.477
  Bottom Layer w1: v1(62.098,21.857) 62.098,19.881 63.143,18.836 218.643,18.836 221.843,22.036 v1(224.643,22.036)
  other v1: 62.098,20.649
+3.3V_C-V_LDO: C339.1 C342.1 R325.2 U305.1 | length 5.1
  Bottom Layer w0.5: C342.1@58.925,23.727 C339.1@60.047,23.727 ; v1@59.924,24.517 v1(59.943,24.536) 59.962,24.517 59.962,23.813 C339.1@60.047,23.727 ; C339.1@60.1,23.675 C339.1@60.047,23.727 ; C339.1@60.1,23.727 62.047,23.727 R325.2@62.1,23.78 62.062,23.818 62.062,24.717 v1(62.043,24.736)
+3.3V_H: C216.1 C217.1 J1000.1 J1001.1 J1002.1 R1019.2 R1020.2 R1021.2 R1027.1 U201.5 | length 210.2
  Top Layer w0.6: v1(65.143,21.736) 65.291,21.588 J1000.1@66.809,21.588 J1000.1@66.861,21.536 ; v1(121.097,22.157) 122.739,22.157 122.809,22.087 J1001.1@122.809,21.588 ; v1(177.36,21.599) 178.798,21.599 J1002.1@178.809,21.588
  Int2 (PWR) w0.6: 52.289,29.236 52.789,29.736 61.643,29.736 64.632,26.748 65.143,26.748 74.154,26.748 ; v1(65.143,21.736) 65.143,26.688 ; 74.197,26.79 75.143,27.736 78.643,27.736 ; v1(78.452,23.6) 78.452,27.546 78.643,27.736 ; v1(121.097,22.157) 119.117,24.136 119.117,25.69 118.93,25.877 ; v1(177.36,21.599) 177.443,21.683 177.443,26.236 ; v1(187.743,27.936) 186.682,27.936 186.282,28.336 179.543,28.336 177.443,26.236 ; 78.643,27.736 114.843,27.736 116.703,25.877 118.93,25.877 ; 118.93,25.877 130.632,25.877 131.561,24.948 135.054,24.948 136.202,26.095 142.844,26.095 143.302,25.636 157.543,25.636 160.343,28.436 171.693,28.436 173.893,26.236 177.443,26.236
  Bottom Layer w0.6: v1(78.452,23.6) 78.452,23.646 78.475,23.668 R1019.2@78.475,25.855 ; v1(121.097,22.157) 124.256,22.157 124.98,21.433 128.598,21.433 131.043,23.879 131.043,25.861 R1020.2@131.218,26.036 ; R1020.2@131.243,26.036 R1020.2@131.218,26.036 ; R1027.1@137.583,48.491 137.558,48.491 135.854,46.786 135.854,33.149 131.043,28.338 131.043,26.211 R1020.2@131.218,26.036 ; R1021.2@187.269,25.1 187.269,27.462 v1(187.743,27.936)
  other v1: 51.443,28.936 50.14,28.95
+3.3V_L: C308.1 C309.1 R116.2 U300.5 | length 2.3
  Top Layer w0.5: v1(50.443,24.636) 50.447,24.633 50.447,23.878 U300.5@50.45,23.875 ; R116.2@52.924,23.758 R116.2@52.924,24.003 ; R116.2@52.978,23.543 52.924,23.597 R116.2@52.924,24.003 ; R116.2@53.25,23.758 53.169,23.758 R116.2@52.924,24.003
  Bottom Layer w0.5: C309.1@49.875,23.725 C309.1@49.875,23.75 ; C308.1@51.175,23.8 C308.1@51.432,23.543
  other v1: 51.849,24.562
+3.3V_L_SF: C1000.2 C1001.2 C1002.2 J1000.3 J1001.3 J1002.3 R115.1 R116.1 R1022.1 R1023.1 R1024.1 R1030.1 U1000.5 U1001.5 U1006.5 | length 211.3
  Top Layer w0.25: R116.1@53.25,22.028 59.942,22.028 61.335,23.421 67.274,23.421 68.079,22.616 J1000.3@68.079,21.588 68.066,21.588 v1(68.026,21.629)
  Top Layer w0.3: U1006.5@146.918,31.136 146.968,31.086 147.374,31.086 147.879,30.582 147.879,29.901 v1(148.843,28.936) ; v1(180.043,23.336) 180.061,23.319 180.061,21.606 J1002.3@180.079,21.588
  Int1 (Sign) w0.5: v1(124.229,20.711) 127.317,20.711 128.046,21.439 139.95,21.439 ; v1(139.95,19.75) 139.95,21.439 ; v1(148.843,28.936) 148.843,27.236 151.128,24.951 151.128,24.944 ; v1(180.043,23.336) 174.841,28.539 160.046,28.539 158.243,26.736 152.921,26.736 151.128,24.944 ; 139.95,21.439 140.722,21.439 142.241,22.959 149.143,22.959 151.128,24.944
  Int4 (Sign) w0.3: v1(145.205,40.276) 149.903,40.276 v1(151.243,38.936)
  Int4 (Sign) w0.4: v1(84.443,23.436) 92.977,23.436 95.577,20.836 117.481,20.836 117.781,20.536 119.724,20.536 119.898,20.711 v1(124.229,20.711)
  Int4 (Sign) w0.5: v1(180.043,23.336) 180.747,22.632 196.639,22.632 197.843,23.836 v1(200.098,23.836)
  Bottom Layer w0.25: v1(68.026,21.629) 68.077,21.68 81.599,21.68 82.043,21.236 R1022.1@84.443,21.236 ; R1030.1@143.143,48.636 143.288,48.491 143.288,46.079 142.543,45.334 142.543,43.936 145.205,41.274 v1(145.205,40.276)
  Bottom Layer w0.3: v1(148.843,28.936) 148.893,28.986 149.593,28.986 149.943,29.336 149.943,29.788 150.949,30.793 C1002.2@150.949,30.818 ; v1(151.243,38.936) 151.243,38.855 151.694,38.405 U1000.5@151.694,36.188 151.763,36.119 151.763,35.45 152.152,35.061 152.718,35.061 C1000.2@153.043,34.736 153.043,33.85 153.657,33.236 154.666,33.236 155.79,32.113 C1001.2@155.79,31.292 ; U1001.5@154.519,31.188 155.894,31.188 C1001.2@155.994,31.088 155.669,30.763 155.669,30.644 155.025,30 155.025,28.78 154.743,28.498 v1(154.743,26.736)
  Bottom Layer w0.5: R1022.1@84.443,21.236 v1(84.443,23.436) ; v1(139.95,19.75) 139.95,21.113 R1023.1@140.02,21.183 ; R1024.1@197.843,24.336 197.843,24.311 198.318,23.836 R115.1@200.593,23.836
+3.3V_LDO: C326.1 C327.1 R324.2 U303.5
  other v1: 60.443,28.236 59.043,28.936 60.443,28.936
+5V: C2.1 C314.1 C315.1 C324.1 C325.1 C340.1 C341.1 C346.1 C607.1 C609.1 C810.2 C903.1 C1301.2 D602.2 FB600.1 FB801.2 J14.27 J15.18 J15.20 J18.1 J23.7 J23.9 L300.2 P1300.4 P1301.4 R59.2 R106.1 R307.2 R1300.2 R1301.2 R1302.2 R1305.2 R1306.2 R1307.2 U2.3 U2.4 U303.1 U303.3 U305.4 U305.6 U603.2 U603.7 U901.1 U1300.15 | length 264
  Top Layer w0.18: v1(149.233,50.624) J15.20@149.233,51.656
  Top Layer w0.25: J15.20@149.233,51.656 J15.20@149.233,51.757 149.233,52.733 149.364,52.864 149.737,52.864 ; J15.18@149.706,51.683 149.733,51.711 J15.18@149.733,51.757 149.737,51.761 149.737,52.864 ; v1(149.741,53.661) 149.737,53.657 149.737,52.864 ; v1(151.982,57.498) 156.252,57.498 157.377,58.622 J14.27@160.829,58.622
  Top Layer w0.3: U303.3@55.925,26.325 56.125,26.325 56.843,27.043 56.843,28.014 ; v1(119.766,57.811) 119.766,58.478 120.2,58.911 120.485,58.911 U2.3@120.635,59.061 ; U2.4@123.385,59.061 125.065,59.061 C2.1@125.205,59.202 126.172,59.202 126.943,59.973 v1(126.943,60.536) ; C1301.2@203.243,40.936 J18.1@203.243,44.696
  Top Layer w0.5: C810.2@199.143,101.952 199.185,101.994 200.601,101.994 FB801.2@200.643,102.036
  Top Layer w0.8: v1(160.443,40.636) 159.863,40.056 J23.9@159.863,37.93 J23.7@162.403,37.93 ; v1(197.143,98.836) 197.143,100.928 197.933,101.717 198.908,101.717 C810.2@199.143,101.952
  Top Layer w1: FB600.1@38.443,71.436 40.043,71.436 v1(40.043,69.836) ; R1300.2@196.491,36.988 196.491,40.579 v1(196.494,40.581) ; C1301.2@203.243,40.936 204.668,40.936 204.803,40.801 P1300.4@204.803,40.096 P1301.4@204.803,33.519 ; R106.1@247.893,48.236 v1(247.993,48.136)
  Int2 (PWR) w0.25: 127.205,57.183 144.45,57.183 145.622,58.355 151.125,58.355 v1(151.982,57.498)
  Int1 (Sign) w0.25: v1(54.443,28.136) 54.443,25.162 54.849,24.757 v1(54.849,24.662)
  Int1 (Sign) w0.5: v1(247.993,48.136) 250.543,48.136 253.265,50.858 v1(253.265,52.004)
  Int1 (Sign) w0.8: v1(197.943,85.236) 200.943,82.236 200.943,54.787 204.643,51.087 204.643,45.836 203.92,45.114 203.66,45.114 J18.1@203.243,44.696
  Int4 (Sign) w0.25: v1(54.849,24.662) 54.881,24.695 56.273,24.695 v1(56.305,24.727)
  Int4 (Sign) w0.8: J18.1@203.243,44.696 203.523,44.417 211.824,44.417 212.543,45.136 244.993,45.136 v1(247.993,48.136)
  Int4 (Sign) w1: v1(38.35,28.346) 38.1,28.596 38.1,59.422 40.043,61.365 v1(40.043,69.836)
  Bottom Layer w0.2: v1(149.233,50.624) 149.242,50.615 R59.2@149.242,48.898
  Bottom Layer w0.25: v1(149.741,53.661) 149.713,53.689 149.713,54.496 151.982,56.764 v1(151.982,57.498) ; v1(193.643,40.636) 193.675,40.605 U1300.15@193.675,37.4
  Bottom Layer w0.3: R307.2@33,26.3 33.32,26.62 33.32,27.327 33.894,27.9 C314.1@35.8,27.9 ; v1(126.943,60.536) 126.843,60.536 C903.1@128.643,60.536
  Bottom Layer w0.5: v1(253.265,52.004) 253.781,52.004 253.835,51.95 U603.7@253.835,57.1 253.835,58.665 C609.1@253.6,58.9 253.637,58.937 D602.2@253.637,61.1
  Bottom Layer w0.8: v1(197.143,98.836) 197.143,86.036 v1(197.943,85.236)
  other v1: 37.7,27.736 39.043,27.936 37.543,28.833 39.043,28.936 54.543,28.936 55.643,28.936 38.1,29.134 50.739,30.6 51.513,30.6 52.31,30.6 53.097,30.6 53.943,30.6 77.343,40.536 78.243,40.936 77.343,41.636 78.243,41.736 78.243,42.536 77.343,42.636 104.043,58.236 107.543,58.636 103.143,59.236 107.143,59.836
+5V_CAN_WU: C602.2 R105.2 R106.2 U601.3 | length 10
  Top Layer w0.2: R105.2@249.623,46.036 R106.2@249.623,48.236 251.026,48.236 251.564,48.775 252.571,48.775 252.775,48.979 252.775,50.4 252,51.175 C602.2@252,51.2 U601.3@252,53
+5V_ISO: C601.1 C608.1 C614.2 J102.9 U600.8 U602.9 U602.10 U602.11 | length 17
  Top Layer w0.6: J102.9@8.08,78.555 8.099,78.536 15.768,78.536 15.943,78.711 C601.1@15.943,78.73 ; C601.1@15.943,78.736 16.048,78.631 U600.8@17.533,78.631 ; C614.2@17.043,74.136 17.909,74.136 18.029,74.016 ; U600.8@17.793,78.631 U600.8@17.533,78.631 ; U602.10@18.343,74.461 U602.9@18.343,75.111 17.885,75.111 17.533,75.463 U600.8@17.533,78.631
  Bottom Layer w0.6: v1(14.643,78.536) 14.843,78.736 15.768,78.736 C608.1@15.943,78.736
+12V_H: C210.1 C211.1 C212.1 C213.1 C214.1 C215.1 C220.1 C221.1 C222.1 C223.1 C224.1 C225.1 C227.1 D900.1 J109.1 J110.1 L200.1 R235.2 R243.2 U201.1 U202.15 U202.16 U203.3 | length 18.1
  Bottom Layer w0.2: C227.1@40.843,51.886 U203.3@40.843,53.443
  Bottom Layer w0.3: C220.1@33,52.225 33.25,51.975 33.25,51.03 34.843,49.436 37.025,49.436 37.875,50.286 R243.2@37.9,50.286 37.925,50.286 38.712,51.074 40.056,51.074 40.843,51.861 C227.1@40.843,51.886
  Bottom Layer w0.5: R235.2@27.35,12.363 27.35,13.514 27.643,13.807 v1(28.036,13.807)
  Bottom Layer w1: D900.1@23.3,25.9 25.695,23.505 25.925,23.505 J110.1@26.2,23.23
  other v1: 28.843,17.536 29.543,17.536 30.243,17.536 45.943,28.036 46.543,28.836 47.461,28.95 32.028,56.15 32.5,56.618 31.443,56.736 32.043,57.136 31.443,57.736 32.5,57.801 31.943,58.336 31.443,58.936 32.5,58.94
